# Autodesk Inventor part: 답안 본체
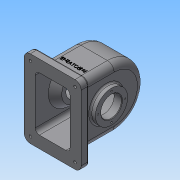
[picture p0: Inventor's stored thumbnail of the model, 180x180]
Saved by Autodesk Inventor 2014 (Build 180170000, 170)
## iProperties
Created: 2016-10
Part Number: 답안 본체
Material: 일반
Document SubType Name: Modeling
Designer: NET
Density: 1 g/cm^3
Appearance: 기본값
Author: NET
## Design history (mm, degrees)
sketch "스케치1"
  geometry: L1 (55, -75)-(-55, -75); L2 (-55, -75)-(-55, 75); L3 (-55, 75)-(55, 75); L4 (55, 75)-(55, -75); 1 further point
  constraints: 8 end point, 2 parallel, 1 horizontal, 1 perpendicular
  dimensions: "d0" = 150 distance of L1.end L2.end; "d1" = 110 distance of L1.start L1.end; "d2" = 55 distance from line of point (0, 0) L2; "d3" = 75 distance from line of point (0, 0) L1
extrude "돌출1" new body sketch "스케치1" distance "d4" = 15; taper "d5" = 0 deg
node "작업 평면1"
sketch "스케치2"
  geometry: L1 (75, 0)-(75, 80); L2 (17, 80)-(17, 7.723); L3 (133, 80)-(133, 7.723); L4 (17, 7.723)-(133, 7.723); A1 r 58 centre (75, 80) between (133, 80) and (17, 80)
  constraints: 8 end point, 2 parallel, 2 point on circle, 2 tangent, 1 centre point, 1 coincident, 1 perpendicular, 1 vertical
  dimensions: "d6" = 80 distance of L1.start L1.end; "d9" = 58 radius of A1; "d21" = 72.27659 distance from line of A1.centre L4
extrude "돌출2" join sketch "스케치2" stored distance "d11" = 77; taper "d12" = 0 deg
sketch "스케치3"
  geometry: L1 (17, 15)-(17, 80) reference; L2 (133, 80)-(133, 15) reference; L3 (0, 0)-(150, 0) reference; L4 (23, 0)-(23, 80); L5 (127, 80)-(127, 0); L6 (23, 0)-(127, 0); A1 r 58 centre (75, 80) between (133, 80) and (17, 80) reference; A2 r 52 centre (75, 80) between (127, 80) and (23, 80); 3 further points
  constraints: 6 end point, 2 point on circle, 2 point on line, 1 centre point, 1 collinear
  dimensions: "d13" = 6 radial gap between concentric circles of A1 A2; "d14" = 80 distance of L5.start L5.end; "d15" = 80 distance of L4.start L4.end; "d16" = 104 distance between parallel lines of L5 L4
extrude "돌출3" cut sketch "스케치3" stored distance "d17" = 67; taper "d18" = 0 deg
node "작업 평면2"
sketch "스케치4"
  geometry: 1 further point
fillet "모깎기1" dims "d19" = 13
fillet "모깎기2" dims "d20" = 8
sketch "스케치5"
  geometry: 1 further point
fillet "모깎기3" dims "d22" = 12
sketch "스케치7"
  geometry: L1 (-12, 0)-(-138, 0) reference; L2 (-133, 80)-(-133, 15) reference; L3 (-75, 0)-(-75, 65); C1 r 37.5 at (-75, 65)
  constraints: 2 end point, 1 centre point, 1 coincident, 1 parallel
  dimensions: "d39" = 65 distance of L3.start L3.end; "d40" = 75 diameter of C1
extrude "돌출4" join sketch "스케치7" distance "d41" = 5; taper "d42" = 0 deg
sketch "스케치8"
  geometry: L1 (120, 80)-(120, 15) reference; L2 (75, 0)-(75, 65); C1 r 31 at (75, 65)
  constraints: 2 end point, 1 centre point, 1 coincident, 1 parallel
  dimensions: "d43" = 65 distance of L2.start L2.end; "d44" = 62 diameter of C1
extrude "돌출5" join sketch "스케치8" distance "d45" = 10; taper "d46" = 0 deg
fillet "모깎기4" dims "d47" = 3
fillet "모깎기5" dims "d48" = 3
sketch "스케치9"
  geometry: C1 r 37.5 at (0, 0) reference; C2 r 20 at (0, 0); 1 further point
  constraints: 1 centre point, 1 coincident
  dimensions: "d49" = 40 diameter of C2
sketch "스케치11" dims "d55" = 58
  geometry: L1 (0, 0)-(0, 29); C1 r 37.5 at (0, 0) reference; 2 further points
  constraints: 2 coincident, 2 end point, 1 vertical, 1 vertical alignment, 2 other
hole "구멍1" sketch "스케치11" at (0, 29) diameter "d56" = 3; stored, may be unused: countersink angle "d60" = 90 deg, drill point angle "d62" = 118 deg; dims "d57" = 6, "d58" = 4, "d59" = 2, "d61" = 8
feature "스레드1" dims "d63" = 6, "d64" = 0
sketch "스케치12" dims "d68" = 52
  geometry: L1 (0, 0)-(0, 26); C1 r 31 at (0, 0) reference; 2 further points
  constraints: 2 coincident, 2 end point, 1 vertical, 1 vertical alignment, 2 other
hole "구멍2" sketch "스케치12" at (0, 26) diameter "d69" = 3; stored, may be unused: countersink angle "d73" = 90 deg, drill point angle "d75" = 118 deg; dims "d70" = 6, "d71" = 4, "d72" = 2, "d74" = 8
feature "스레드2" dims "d76" = 6, "d77" = 0
fillet "모깎기6" dims "d81" = 3
fillet "모깎기7" dims "d82" = 3
hole "구멍3" diameter "d85" = 5; stored, may be unused: countersink angle "d89" = 90 deg, drill point angle "d91" = 118 deg; dims "d83" = 10, "d84" = 10, "d86" = 6, "d87" = 12, "d88" = 5, "d90" = 8
node "작업 평면3"
sketch "스케치13"
  geometry: C1 r 6 at (0, 0); 1 further point
  constraints: 1 centre point, 1 coincident
  dimensions: "d93" = 12 diameter of C1
extrude "돌출8" join sketch "스케치13" stored distance "d94" = 15; taper "d95" = 0 deg
feature "면 기울기1" dims angle "d96" = 10 deg
fillet "모깎기8" dims "d97" = 3
hole "구멍4" diameter "d100" = 4.459; stored, may be unused: countersink angle "d104" = 90 deg, drill point angle "d106" = 118 deg; dims "d98" = 10, "d99" = 10, "d101" = 25, "d102" = 12, "d103" = 5, "d105" = 8
sketch "스케치14"
  geometry: L1 (68.5, -80)-(-17.5, -80) reference; L2 (-13, 0)-(-13, -62) reference; 2 further points
  constraints: 1 other
  dimensions: "d112" = 40 distance from line of L1 point (25.5, -40); "d113" = 38.5 distance from line of point (25.5, -40) L2
feature "엠보싱1" sketch "스케치14" dims "d11" = 77, "d114" = 0.5, "d115" = 0
sketch "스케치15"
  geometry: 1 further point
sketch "스케치16"
  geometry: L1 (12, 0)-(98, 0) reference; L2 (21.5, 65)-(35.5, 65); L3 (21.5, 124)-(21.5, 80) reference; L4 (21.5, 80)-(21.5, 0) reference; L5 (35.5, 65)-(35.5, 93); L6 (35.5, 93)-(21.5, 104.747); L7 (21.5, 104.747)-(21.5, 65); 1 further point
  constraints: 8 end point, 2 point on line, 1 parallel
  dimensions: "d125" = 65 distance between parallel lines of L1 L2; "d128" = 50 deg angle of L5 L6; "d129" = 28 distance of L2.end L5.end; "d130" = 14 horizontal distance of L5.end L6.end; "d131" = 14 distance of L2.start L2.end
revolve "회전6" sketch "스케치16" stored, may be unused: angle "d132" = 90 deg
extrude "돌출13" cut sketch "스케치9" stored distance "d133" = 10; taper "d134" = 0 deg
chamfer "모따기1" distance "d135" = 1; stored, may be unused: second distance "d136" = 2, angle "d137" = 45 deg
chamfer "모따기2" distance "d138" = 1; stored, may be unused: second distance "d139" = 2, angle "d140" = 45 deg
node "솔리드1"
pattern_circular "원형 패턴1" dims angle "d66" = 360 deg
pattern_circular "원형 패턴2" dims angle "d79" = 360 deg
mirror "대칭1"
mirror "대칭2"
other parameters: "d92" = -144
